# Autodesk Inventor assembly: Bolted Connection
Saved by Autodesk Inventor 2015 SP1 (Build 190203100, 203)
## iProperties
Created: 2014-12
Part Number: Bolted Connection
Document SubType Name: Assembly
Designer: rsheridan
ClientObjectVersion: 1
Author: rsheridan
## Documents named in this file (4)
- \\psf\Home\Documents\Inventor\Sau Paulo Chimnea\Base Assembly\Design Accelerator\Bolted Connection1.iam
- \\mcl_camd\camd\RSheridan\My Documents\Inventor\Content Center Files\R2015\en-US\ISO 7046-2 H\ISO 7046-2 H - M5x35 - 8.8 - H1.ipt
- \\psf\Home\Documents\Inventor\Sau Paulo Chimnea\ISO 7089 - 5 - 140 HV(1).ipt
- \\psf\Home\Documents\Inventor\Sau Paulo Chimnea\ISO 4032 - M5ISO.ipt
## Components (9 placed, 3 different names)
1. ISO 7046-2 H M5x35 - 8.8 - H1:1
2. ISO 7089 - 5 - 140 HV(1):1
3. ISO 4032 - M5ISO:1
4. ISO 7046-2 H M5x35 - 8.8 - H1:2
5. ISO 7046-2 H M5x35 - 8.8 - H1:3
6. ISO 7089 - 5 - 140 HV(1):2
7. ISO 7089 - 5 - 140 HV(1):3
8. ISO 4032 - M5ISO:2
9. ISO 4032 - M5ISO:3
